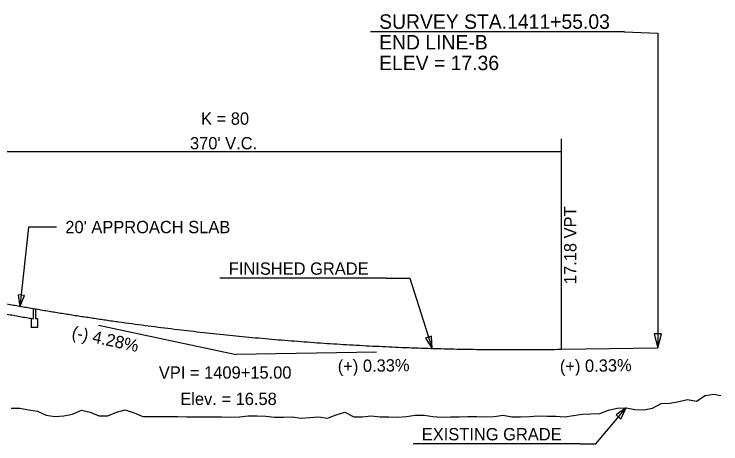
# Model space of a CAD drawing. Extents: x 2360994 to 2383826, y 330623 to 403123.
# Drawn here: x 2370514.3 to 2370916.5, y 346904.9 to 347149.5 of the extents above; entities that cross this region are included whole.
import ezdxf

# ---------------------------------------------------------------- set-up
doc = ezdxf.new("R2010")
doc.units = 0
for name, color, linetype in [('RD_DDB_GradeTX', 7, 'Continuous'), ('RD_DDB_Profile_EX', 7, 'Continuous'), ('RD_DDB_Profile_Lbl', 7, 'Continuous'), ('RD_DDB_Profile_PR', 7, 'Continuous'), ('RD_DDB_StripGrade', 7, 'Continuous'), ('RD_DDB_VCLbl', 7, 'Continuous'), ('RD_TX_Profile', 7, 'Continuous'), ('RD_XS_Bridge', 7, 'Continuous')]:
    doc.layers.add(name, color=color, linetype=linetype)

msp = doc.modelspace()

# ---------------------------------------------------------------- linework, layer by layer
at = {"layer": 'RD_DDB_GradeTX'}
for p in [(2370562.34, 346972.51), (2370720.56, 346957.07)]:
    msp.add_line(p, (2370640.57, 346955.77), dxfattribs=at)
at = {"layer": 'RD_DDB_Profile_EX'}
for points in [[(2370842.54, 346921.96), (2370847.54, 346922.17), (2370852.54, 346924.08), (2370857.54, 346925.17), (2370862.54, 346925.38), (2370867.54, 346924.4), (2370872.54, 346924.29), (2370877.54, 346925.3), (2370882.54, 346927.97), (2370887.54, 346928.13), (2370892.54, 346929.1), (2370897.54, 346930.16), (2370902.54, 346929.29), (2370907.54, 346932.46), (2370912.54, 346933.14), (2370916.47, 346932.42)], [(2370512.54, 346925.33), (2370517.54, 346925.21), (2370522.54, 346924.36), (2370527.54, 346923.51), (2370532.54, 346921.19), (2370537.54, 346920.54), (2370542.54, 346920.91), (2370547.54, 346921.75), (2370552.54, 346924.16), (2370557.54, 346923.04), (2370562.54, 346920.84), (2370567.54, 346920.84), (2370572.54, 346923.02), (2370577.54, 346924.35), (2370582.54, 346922.6), (2370587.54, 346920.41), (2370592.54, 346920.53), (2370597.54, 346920.52), (2370602.54, 346920.59), (2370607.54, 346920.49), (2370612.54, 346920.26), (2370617.54, 346920.34), (2370622.54, 346920.28), (2370627.54, 346920.34), (2370632.54, 346920.23), (2370637.54, 346920.07), (2370642.54, 346920.27), (2370647.54, 346920.91), (2370652.54, 346920.95), (2370657.54, 346920.67), (2370662.54, 346920.14), (2370667.54, 346920.12), (2370672.54, 346920.29), (2370677.54, 346919.54), (2370682.54, 346919.91), (2370687.54, 346920.24), (2370692.54, 346919.51), (2370697.54, 346921.43), (2370702.54, 346922.91), (2370707.54, 346920.39), (2370712.54, 346920.38), (2370717.54, 346920.94), (2370722.54, 346920.36), (2370727.54, 346920.26), (2370732.54, 346920.1), (2370737.54, 346920.56), (2370742.54, 346921.27), (2370747.54, 346921.18), (2370752.54, 346920.57), (2370757.54, 346920.15), (2370762.54, 346920.38), (2370767.54, 346920.38), (2370772.54, 346920.43), (2370777.54, 346920.42), (2370782.54, 346920.37), (2370787.54, 346920.58), (2370792.54, 346921.26), (2370797.54, 346920.38), (2370802.54, 346920.38), (2370807.54, 346920.56), (2370812.54, 346920.85), (2370817.54, 346920.74), (2370822.54, 346920.67), (2370827.54, 346920.4), (2370832.54, 346921.11), (2370837.54, 346921.85), (2370842.54, 346921.96)]]:
    msp.add_lwpolyline(points, dxfattribs=at)
at = {"layer": 'RD_DDB_Profile_PR'}
msp.add_line((2370825.57, 346958.78), (2370880.6, 346959.68), dxfattribs=at)
msp.add_spline([(2370455.57, 346995.36), (2370462.97, 346993.79), (2370470.37, 346992.26), (2370477.77, 346990.76), (2370485.17, 346989.3), (2370492.57, 346987.87), (2370499.97, 346986.47), (2370507.37, 346985.11), (2370514.77, 346983.78), (2370522.17, 346982.49), (2370529.57, 346981.23), (2370536.97, 346980), (2370544.37, 346978.81), (2370551.77, 346977.65), (2370559.17, 346976.53), (2370566.57, 346975.44), (2370573.97, 346974.38), (2370581.37, 346973.36), (2370588.77, 346972.38), (2370596.17, 346971.42), (2370603.57, 346970.5), (2370610.97, 346969.62), (2370618.37, 346968.77), (2370625.77, 346967.95), (2370633.17, 346967.17), (2370640.57, 346966.42), (2370647.97, 346965.71), (2370655.37, 346965.03), (2370662.77, 346964.38), (2370670.17, 346963.77), (2370677.57, 346963.19), (2370684.97, 346962.65), (2370692.37, 346962.14), (2370699.77, 346961.66), (2370707.17, 346961.22), (2370714.57, 346960.81), (2370721.97, 346960.44), (2370729.37, 346960.1), (2370736.77, 346959.79), (2370744.17, 346959.52), (2370751.57, 346959.28), (2370758.97, 346959.08), (2370766.37, 346958.91), (2370773.77, 346958.78), (2370781.17, 346958.67), (2370788.57, 346958.61), (2370795.97, 346958.57), (2370803.37, 346958.58), (2370810.77, 346958.61), (2370818.17, 346958.68), (2370825.57, 346958.78)], degree=3, dxfattribs=at)
at = {"layer": 'RD_DDB_VCLbl'}
for p, q in [((2370825.57, 347078.53), (2370825.57, 346958.78)), ((2370455.57, 347071.32), (2370825.57, 347071.32))]:
    msp.add_line(p, q, dxfattribs=at)
at = {"layer": 'RD_TX_Profile'}
for p, q in [((2370861.55, 347139.39), (2370717, 347139.39)), ((2370726.01, 346999.19), (2370631.44, 346999.19)), ((2370836.41, 346904.93), (2370741.28, 346904.93))]:
    msp.add_line(p, q, dxfattribs=at)
for points in [[(2370861.55, 347139.39), (2370880.68, 347138.7), (2370880.6, 346959.68)], [(2370538.44, 347028.34), (2370522.52, 347028.34), (2370517.63, 346982.9)], [(2370726.01, 346999.19), (2370739.39, 346999.19), (2370752.17, 346959.25)], [(2370836.41, 346904.93), (2370845.41, 346904.93), (2370862.54, 346925.38)]]:
    msp.add_lwpolyline(points, dxfattribs=at)
for points in [[(2370516.55, 346989.82), (2370517.63, 346982.9), (2370520.15, 346989.43)], [(2370878.47, 346967.64), (2370880.6, 346959.68), (2370882.73, 346967.63)], [(2370748.38, 346965.14), (2370752.17, 346959.25), (2370751.83, 346966.24)], [(2370859.58, 346919.03), (2370862.54, 346925.38), (2370856.81, 346921.36)]]:
    msp.add_lwpolyline(points, close=True, dxfattribs=at)
at = {"layer": 'RD_XS_Bridge'}
for p, q in [((2370525.08, 346981.99), (2370525.08, 346976.15)), ((2370526.41, 346981.76), (2370526.41, 346976.14)), ((2370523.91, 346976.35), (2370523.91, 346971.14)), ((2370527.66, 346976.14), (2370526.41, 346976.14)), ((2370527.66, 346976.14), (2370527.66, 346971.14)), ((2370527.66, 346971.14), (2370523.91, 346971.14))]:
    msp.add_line(p, q, dxfattribs=at)
msp.add_spline([(2370505.08, 346979.69), (2370507.37, 346979.28), (2370514.77, 346977.95), (2370522.17, 346976.65), (2370525.08, 346976.15)], degree=3, dxfattribs=at)

# ---------------------------------------------------------------- texts
at = {"layer": 'RD_DDB_GradeTX'}
for s, rotation, p in [('(-) 4.28%', 347.921, (2370546.67, 346965.22)), ('(+) 0.33%', 0.9336, (2370698.51, 346945.63)), ('(+) 0.33%', 0.9336, (2370824.91, 346945.63))]:
    msp.add_text(s, height=7, rotation=rotation, dxfattribs=at).set_placement(p)
at = {"layer": 'RD_DDB_Profile_Lbl'}
for s, p in [('VPI = 1409+15.00', (2370596.65, 346942.04)), ('Elev. = 16.58', (2370608.85, 346927.04))]:
    msp.add_text(s, height=7, dxfattribs=at).set_placement(p)
at = {"layer": 'RD_DDB_StripGrade'}
msp.add_text('17.18 VPT', height=7, rotation=90, dxfattribs=at).set_placement((2370834.25, 346995.83))
at = {"layer": 'RD_DDB_VCLbl'}
for s, p in [('K = 80', (2370620.67, 347086.57)), ("370' V.C.", (2370614.37, 347072.57))]:
    msp.add_text(s, height=7, dxfattribs=at).set_placement(p)
at = {"layer": 'RD_TX_Profile'}
for s, height, p in [('SURVEY STA.1411+55.03', 8.2353, (2370722, 347141.15)), ('END LINE-B', 8.235, (2370722, 347129.39)), ('ELEV = 17.36', 8.2353, (2370722, 347117.62)), ("20' APPROACH SLAB", 7, (2370543.44, 347024.84)), ('FINISHED GRADE', 7, (2370636.44, 347001.19)), ('EXISTING GRADE', 7, (2370746.28, 346906.93))]:
    msp.add_text(s, height=height, dxfattribs=at).set_placement(p)

doc.saveas('drawing.dxf')
